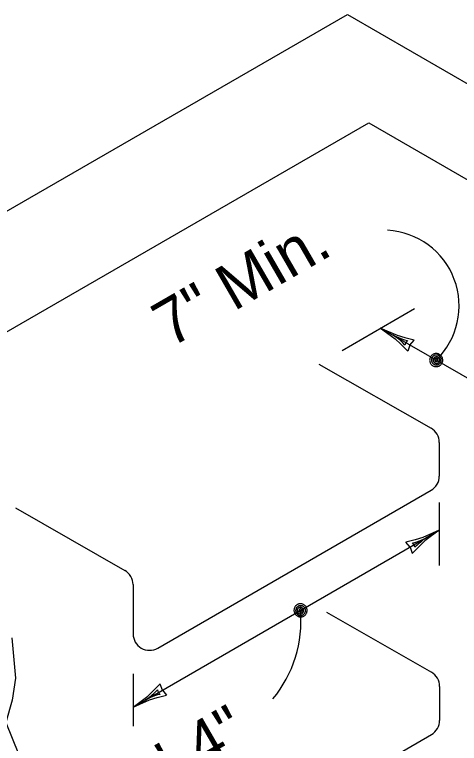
# Model space of a CAD drawing. Extents: x -7.1 to 10, y -5 to 6.
# Drawn here: x 3.017 to 3.657, y 3.525 to 4.574 of the extents above; entities that cross this region are included whole.
import ezdxf

# ---------------------------------------------------------------- set-up
doc = ezdxf.new("R2010")
doc.units = 0
for name, color, linetype in [('Level 4', 7, 'Continuous'), ('Level 6', 7, 'Continuous'), ('Level 7', 7, 'Continuous')]:
    doc.layers.add(name, color=color, linetype=linetype)

msp = doc.modelspace()

# ---------------------------------------------------------------- linework, layer by layer
at = {"layer": 'Level 4'}
for p, q in [((2.3265, 3.8986), (3.4958, 4.5737)), ((3.4958, 4.5737), (4.161, 4.1897)), ((2.6278, 3.899), (3.5265, 4.4179)), ((3.5265, 4.4179), (4.0246, 4.1304)), ((3.4545, 4.0707), (3.616, 3.9783)), ((3.6279, 3.9578), (3.6279, 3.9095)), ((3.2229, 3.662), (3.6161, 3.8891)), ((3.0185, 3.8636), (3.1755, 3.7737)), ((3.1874, 3.7532), (3.1874, 3.6824)), ((3.4656, 3.7135), (3.6165, 3.6272)), ((3.6284, 3.6067), (3.6284, 3.5579)), ((3.2494, 3.3255), (3.6166, 3.5375))]:
    msp.add_line(p, q, dxfattribs=at)
msp.add_lwpolyline([(3.0129, 3.6767), (3.0182, 3.6185), (3.0137, 3.5868), (3.0046, 3.555), (3.0227, 3.5097), (3.0273, 3.4961), (3.0227, 3.419), (3.0091, 3.3872), (3.0227, 3.292), (3.0227, 3.2466), (3.0091, 3.2285), (3.0273, 3.174), (3.0273, 3.1559), (3.0001, 3.0924), (3.0091, 3.047), (3.0182, 3.0198), (3.0137, 2.9654), (3.0156, 2.8939)], dxfattribs=at)
for centre, start, end in [((3.6043, 3.9578), 0, 60.2358), ((3.6043, 3.9095), 300.0053, 360), ((3.1638, 3.7532), 0, 60.2326), ((3.2111, 3.6824), 180, 300.0049), ((3.6048, 3.6067), 0, 60.239), ((3.6048, 3.5579), 300.0041, 360)]:
    msp.add_arc(centre, 0.0236, start, end, dxfattribs=at)
at = {"layer": 'Level 7'}
for p, q in [((3.4882, 4.0903), (3.592, 4.1509)), ((3.7166, 4.0226), (3.5435, 4.1226)), ((3.5854, 4.0981), (3.5916, 4.1051)), ((3.5854, 4.0981), (3.5825, 4.0893)), ((3.6279, 3.8715), (3.6279, 3.7806)), ((3.1874, 3.5771), (3.6279, 3.8315)), ((3.5858, 3.8073), (3.5797, 3.8143)), ((3.5858, 3.8073), (3.5887, 3.7986)), ((3.1874, 3.6251), (3.1874, 3.5493)), ((3.2296, 3.6012), (3.2266, 3.61)), ((3.2296, 3.6012), (3.2357, 3.5943))]:
    msp.add_line(p, q, dxfattribs=at)
for points in [[(3.5435, 4.1226), (3.5645, 4.1072), (3.5726, 4.0994), (3.5825, 4.0893)], [(3.5435, 4.1226), (3.5673, 4.1121), (3.5781, 4.1089), (3.5919, 4.1056)], [(3.5614, 4.1123), (3.5676, 4.1093), (3.5717, 4.1079), (3.5751, 4.1064), (3.5779, 4.1057), (3.5821, 4.1045), (3.5796, 4.1017), (3.5784, 4.098), (3.5761, 4.1009), (3.5741, 4.1028), (3.5719, 4.1045), (3.5699, 4.1064), (3.5679, 4.1078), (3.5656, 4.1095), (3.5614, 4.1123)], [(3.6279, 3.8315), (3.6041, 3.8209), (3.5933, 3.8178), (3.5797, 3.8143)], [(3.6279, 3.8315), (3.6069, 3.8161), (3.5988, 3.8083), (3.589, 3.798)], [(3.6101, 3.8211), (3.6044, 3.8172), (3.6011, 3.8143), (3.5982, 3.8122), (3.5961, 3.8101), (3.5929, 3.807), (3.5918, 3.8106), (3.5892, 3.8135), (3.5929, 3.814), (3.5955, 3.8148), (3.5981, 3.8159), (3.6007, 3.8167), (3.6029, 3.8177), (3.6056, 3.8188), (3.6101, 3.8211)], [(3.1874, 3.5771), (3.2085, 3.5925), (3.2166, 3.6003), (3.2263, 3.6106)], [(3.2053, 3.5874), (3.211, 3.5914), (3.2143, 3.5942), (3.2172, 3.5964), (3.2193, 3.5985), (3.2224, 3.6016), (3.2236, 3.598), (3.2262, 3.595), (3.2225, 3.5945), (3.2199, 3.5938), (3.2173, 3.5927), (3.2147, 3.5919), (3.2124, 3.5908), (3.2098, 3.5898), (3.2053, 3.5874)], [(3.1874, 3.5771), (3.2113, 3.5876), (3.2221, 3.5908), (3.2357, 3.5943)]]:
    msp.add_lwpolyline(points, dxfattribs=at)
for points in [[(3.6163, 4.0703), (3.6168, 4.0697), (3.6174, 4.0691), (3.6181, 4.0686), (3.6188, 4.0682), (3.6195, 4.0678), (3.6203, 4.0675), (3.6211, 4.0673), (3.6219, 4.0671), (3.6227, 4.067), (3.6235, 4.067), (3.6243, 4.067), (3.6251, 4.0671), (3.6259, 4.0673), (3.6267, 4.0676), (3.6275, 4.0679), (3.6282, 4.0683), (3.6289, 4.0687), (3.6296, 4.0692), (3.6302, 4.0698), (3.6307, 4.0704), (3.6312, 4.071), (3.6316, 4.0717), (3.632, 4.0725), (3.6323, 4.0732), (3.6326, 4.074), (3.6328, 4.0748), (3.6329, 4.0756), (3.6329, 4.0765), (3.6328, 4.0773), (3.6327, 4.0781), (3.6326, 4.0789), (3.6323, 4.0797), (3.632, 4.0804), (3.6316, 4.0812), (3.6311, 4.0819), (3.6306, 4.0825), (3.6301, 4.0831), (3.6295, 4.0837), (3.6288, 4.0842), (3.6281, 4.0846), (3.6274, 4.085), (3.6266, 4.0853), (3.6258, 4.0855), (3.625, 4.0857), (3.6242, 4.0858), (3.6234, 4.0858), (3.6226, 4.0858), (3.6218, 4.0857), (3.621, 4.0855), (3.6202, 4.0853), (3.6194, 4.0849), (3.6187, 4.0846), (3.618, 4.0841), (3.6173, 4.0836), (3.6168, 4.083), (3.6162, 4.0824), (3.6157, 4.0818), (3.6153, 4.0811), (3.6149, 4.0803), (3.6146, 4.0796), (3.6143, 4.0788), (3.6142, 4.078), (3.6141, 4.0772), (3.614, 4.0764), (3.6141, 4.0755), (3.6142, 4.0747), (3.6144, 4.0739), (3.6146, 4.0731), (3.6149, 4.0724), (3.6153, 4.0716), (3.6158, 4.071)], [(3.6183, 4.0721), (3.6188, 4.0716), (3.6192, 4.0712), (3.6197, 4.0708), (3.6202, 4.0705), (3.6208, 4.0702), (3.6213, 4.07), (3.6219, 4.0698), (3.6225, 4.0697), (3.6231, 4.0696), (3.6238, 4.0696), (3.6244, 4.0696), (3.625, 4.0697), (3.6256, 4.0698), (3.6262, 4.07), (3.6268, 4.0702), (3.6273, 4.0705), (3.6278, 4.0709), (3.6283, 4.0712), (3.6288, 4.0717), (3.6292, 4.0721), (3.6295, 4.0726), (3.6299, 4.0731), (3.6302, 4.0737), (3.6304, 4.0743), (3.6306, 4.0748), (3.6307, 4.0754), (3.6308, 4.0761), (3.6308, 4.0767), (3.6308, 4.0773), (3.6307, 4.0779), (3.6305, 4.0785), (3.6304, 4.0791), (3.6301, 4.0797), (3.6298, 4.0802), (3.6295, 4.0807), (3.6291, 4.0812), (3.6287, 4.0817), (3.6282, 4.0821), (3.6278, 4.0825), (3.6272, 4.0828), (3.6267, 4.0831), (3.6261, 4.0833), (3.6255, 4.0835), (3.6249, 4.0836), (3.6243, 4.0837), (3.6237, 4.0837), (3.6231, 4.0837), (3.6225, 4.0836), (3.6219, 4.0835), (3.6213, 4.0833), (3.6207, 4.083), (3.6201, 4.0827), (3.6196, 4.0824), (3.6191, 4.082), (3.6187, 4.0816), (3.6183, 4.0812), (3.6179, 4.0807), (3.6176, 4.0801), (3.6173, 4.0796), (3.6171, 4.079), (3.6169, 4.0784), (3.6168, 4.0778), (3.6167, 4.0772), (3.6166, 4.0766), (3.6167, 4.076), (3.6168, 4.0754), (3.6169, 4.0748), (3.6171, 4.0742), (3.6173, 4.0736), (3.6176, 4.0731), (3.6179, 4.0725)], [(3.6204, 4.0733), (3.6206, 4.073), (3.6209, 4.0727), (3.6213, 4.0725), (3.6216, 4.0723), (3.622, 4.0721), (3.6224, 4.0719), (3.6228, 4.0718), (3.6232, 4.0717), (3.6236, 4.0717), (3.624, 4.0717), (3.6244, 4.0717), (3.6248, 4.0717), (3.6252, 4.0718), (3.6256, 4.0719), (3.626, 4.0721), (3.6263, 4.0723), (3.6267, 4.0725), (3.627, 4.0728), (3.6273, 4.0731), (3.6276, 4.0734), (3.6278, 4.0737), (3.6281, 4.074), (3.6282, 4.0744), (3.6284, 4.0748), (3.6285, 4.0752), (3.6286, 4.0756), (3.6287, 4.076), (3.6287, 4.0764), (3.6286, 4.0768), (3.6286, 4.0772), (3.6285, 4.0776), (3.6284, 4.078), (3.6282, 4.0784), (3.628, 4.0788), (3.6278, 4.0791), (3.6276, 4.0794), (3.6273, 4.0797), (3.627, 4.08), (3.6266, 4.0803), (3.6263, 4.0805), (3.6259, 4.0807), (3.6255, 4.0808), (3.6251, 4.0809), (3.6247, 4.081), (3.6243, 4.0811), (3.6239, 4.0811), (3.6235, 4.0811), (3.6231, 4.081), (3.6227, 4.0809), (3.6223, 4.0808), (3.6219, 4.0806), (3.6216, 4.0804), (3.6212, 4.0802), (3.6209, 4.08), (3.6206, 4.0797), (3.6203, 4.0794), (3.6201, 4.0791), (3.6199, 4.0787), (3.6197, 4.0783), (3.6195, 4.078), (3.6194, 4.0776), (3.6193, 4.0772), (3.6193, 4.0768), (3.6192, 4.0763), (3.6193, 4.0759), (3.6193, 4.0755), (3.6194, 4.0751), (3.6195, 4.0747), (3.6197, 4.0744), (3.6199, 4.074), (3.6201, 4.0736)], [(3.6219, 4.0751), (3.6221, 4.075), (3.6222, 4.0748), (3.6224, 4.0747), (3.6226, 4.0746), (3.6227, 4.0745), (3.6229, 4.0744), (3.6231, 4.0744), (3.6233, 4.0743), (3.6235, 4.0743), (3.6237, 4.0743), (3.6239, 4.0743), (3.6241, 4.0743), (3.6243, 4.0744), (3.6245, 4.0744), (3.6247, 4.0745), (3.6249, 4.0746), (3.6251, 4.0747), (3.6253, 4.0748), (3.6254, 4.075), (3.6255, 4.0751), (3.6257, 4.0753), (3.6258, 4.0755), (3.6259, 4.0757), (3.6259, 4.0758), (3.626, 4.076), (3.6261, 4.0762), (3.6261, 4.0764), (3.6261, 4.0766), (3.6261, 4.0769), (3.626, 4.0771), (3.626, 4.0773), (3.6259, 4.0775), (3.6259, 4.0776), (3.6258, 4.0778), (3.6256, 4.078), (3.6255, 4.0782), (3.6254, 4.0783), (3.6252, 4.0784), (3.6251, 4.0786), (3.6249, 4.0787), (3.6247, 4.0788), (3.6245, 4.0789), (3.6243, 4.0789), (3.6241, 4.079), (3.6239, 4.079), (3.6237, 4.079), (3.6235, 4.079), (3.6233, 4.079), (3.6231, 4.0789), (3.6229, 4.0788), (3.6227, 4.0788), (3.6225, 4.0787), (3.6224, 4.0786), (3.6222, 4.0784), (3.622, 4.0783), (3.6219, 4.0781), (3.6218, 4.078), (3.6217, 4.0778), (3.6216, 4.0776), (3.6215, 4.0774), (3.6214, 4.0772), (3.6214, 4.077), (3.6214, 4.0768), (3.6214, 4.0766), (3.6214, 4.0764), (3.6214, 4.0762), (3.6214, 4.076), (3.6215, 4.0758), (3.6216, 4.0756), (3.6217, 4.0754), (3.6218, 4.0753)], [(3.4278, 3.7256), (3.4269, 3.7256), (3.4261, 3.7254), (3.4253, 3.7252), (3.4246, 3.7249), (3.4238, 3.7245), (3.4231, 3.7241), (3.4225, 3.7236), (3.4219, 3.7231), (3.4213, 3.7225), (3.4208, 3.7218), (3.4203, 3.7211), (3.4199, 3.7204), (3.4196, 3.7197), (3.4193, 3.7189), (3.4191, 3.7181), (3.419, 3.7173), (3.4189, 3.7164), (3.4189, 3.7156), (3.419, 3.7148), (3.4192, 3.714), (3.4194, 3.7132), (3.4197, 3.7124), (3.4201, 3.7117), (3.4205, 3.711), (3.421, 3.7103), (3.4215, 3.7097), (3.4221, 3.7091), (3.4228, 3.7086), (3.4235, 3.7082), (3.4242, 3.7078), (3.4249, 3.7074), (3.4257, 3.7072), (3.4265, 3.707), (3.4273, 3.7069), (3.4281, 3.7068), (3.429, 3.7068), (3.4298, 3.7069), (3.4306, 3.7071), (3.4314, 3.7073), (3.4322, 3.7076), (3.4329, 3.7079), (3.4336, 3.7084), (3.4343, 3.7089), (3.4349, 3.7094), (3.4354, 3.71), (3.436, 3.7106), (3.4364, 3.7113), (3.4368, 3.712), (3.4372, 3.7128), (3.4374, 3.7136), (3.4376, 3.7144), (3.4377, 3.7152), (3.4378, 3.716), (3.4378, 3.7168), (3.4377, 3.7176), (3.4375, 3.7185), (3.4373, 3.7192), (3.437, 3.72), (3.4366, 3.7208), (3.4362, 3.7215), (3.4357, 3.7221), (3.4352, 3.7227), (3.4346, 3.7233), (3.434, 3.7238), (3.4333, 3.7243), (3.4326, 3.7247), (3.4318, 3.725), (3.431, 3.7253), (3.4302, 3.7255), (3.4294, 3.7256), (3.4286, 3.7257)], [(3.4279, 3.7229), (3.4273, 3.7229), (3.4267, 3.7228), (3.4261, 3.7226), (3.4256, 3.7224), (3.425, 3.7221), (3.4245, 3.7218), (3.424, 3.7214), (3.4235, 3.721), (3.4231, 3.7206), (3.4227, 3.7201), (3.4223, 3.7196), (3.4221, 3.719), (3.4218, 3.7184), (3.4216, 3.7179), (3.4214, 3.7173), (3.4214, 3.7167), (3.4213, 3.716), (3.4213, 3.7154), (3.4214, 3.7148), (3.4215, 3.7142), (3.4217, 3.7136), (3.4219, 3.713), (3.4222, 3.7125), (3.4225, 3.7119), (3.4229, 3.7115), (3.4233, 3.711), (3.4237, 3.7106), (3.4242, 3.7102), (3.4247, 3.7098), (3.4253, 3.7095), (3.4258, 3.7093), (3.4264, 3.7091), (3.427, 3.7089), (3.4276, 3.7088), (3.4282, 3.7088), (3.4288, 3.7088), (3.4295, 3.7089), (3.4301, 3.709), (3.4307, 3.7092), (3.4312, 3.7094), (3.4318, 3.7097), (3.4323, 3.71), (3.4328, 3.7103), (3.4333, 3.7108), (3.4337, 3.7112), (3.4341, 3.7117), (3.4344, 3.7122), (3.4347, 3.7127), (3.435, 3.7133), (3.4352, 3.7139), (3.4353, 3.7145), (3.4354, 3.7151), (3.4355, 3.7157), (3.4354, 3.7163), (3.4354, 3.7169), (3.4353, 3.7175), (3.4351, 3.7181), (3.4349, 3.7187), (3.4346, 3.7193), (3.4343, 3.7198), (3.4339, 3.7203), (3.4335, 3.7208), (3.4331, 3.7212), (3.4326, 3.7216), (3.4321, 3.7219), (3.4315, 3.7222), (3.431, 3.7225), (3.4304, 3.7227), (3.4298, 3.7228), (3.4292, 3.7229), (3.4286, 3.7229)], [(3.4277, 3.7206), (3.4273, 3.7205), (3.4269, 3.7204), (3.4265, 3.7203), (3.4261, 3.7202), (3.4258, 3.72), (3.4254, 3.7198), (3.4251, 3.7195), (3.4248, 3.7193), (3.4245, 3.719), (3.4242, 3.7186), (3.424, 3.7183), (3.4238, 3.7179), (3.4236, 3.7176), (3.4235, 3.7172), (3.4234, 3.7168), (3.4234, 3.7164), (3.4233, 3.716), (3.4233, 3.7156), (3.4234, 3.7151), (3.4235, 3.7147), (3.4236, 3.7143), (3.4237, 3.714), (3.4239, 3.7136), (3.4241, 3.7132), (3.4244, 3.7129), (3.4246, 3.7126), (3.4249, 3.7123), (3.4252, 3.7121), (3.4256, 3.7118), (3.4259, 3.7116), (3.4263, 3.7115), (3.4267, 3.7113), (3.4271, 3.7112), (3.4275, 3.7112), (3.4279, 3.7111), (3.4283, 3.7111), (3.4288, 3.7112), (3.4292, 3.7113), (3.4296, 3.7114), (3.4299, 3.7115), (3.4303, 3.7117), (3.4307, 3.7119), (3.431, 3.7122), (3.4313, 3.7124), (3.4316, 3.7127), (3.4318, 3.7131), (3.4321, 3.7134), (3.4323, 3.7138), (3.4324, 3.7141), (3.4326, 3.7145), (3.4327, 3.7149), (3.4327, 3.7153), (3.4328, 3.7157), (3.4328, 3.7162), (3.4327, 3.7166), (3.4326, 3.717), (3.4325, 3.7174), (3.4324, 3.7177), (3.4322, 3.7181), (3.432, 3.7185), (3.4317, 3.7188), (3.4314, 3.7191), (3.4312, 3.7194), (3.4308, 3.7196), (3.4305, 3.7199), (3.4301, 3.7201), (3.4298, 3.7202), (3.4294, 3.7204), (3.429, 3.7205), (3.4286, 3.7205), (3.4281, 3.7206)], [(3.4282, 3.7182), (3.428, 3.7182), (3.4278, 3.7182), (3.4276, 3.7181), (3.4274, 3.718), (3.4273, 3.7179), (3.4271, 3.7178), (3.4269, 3.7177), (3.4268, 3.7176), (3.4266, 3.7174), (3.4265, 3.7173), (3.4264, 3.7171), (3.4263, 3.7169), (3.4262, 3.7167), (3.4261, 3.7165), (3.4261, 3.7163), (3.426, 3.7161), (3.426, 3.7159), (3.426, 3.7157), (3.4261, 3.7155), (3.4261, 3.7153), (3.4262, 3.7151), (3.4262, 3.7149), (3.4263, 3.7147), (3.4264, 3.7146), (3.4266, 3.7144), (3.4267, 3.7143), (3.4268, 3.7141), (3.427, 3.714), (3.4272, 3.7139), (3.4273, 3.7138), (3.4275, 3.7137), (3.4277, 3.7136), (3.4279, 3.7136), (3.4281, 3.7135), (3.4283, 3.7135), (3.4285, 3.7135), (3.4288, 3.7135), (3.4289, 3.7136), (3.4291, 3.7136), (3.4293, 3.7137), (3.4295, 3.7138), (3.4297, 3.7139), (3.4299, 3.714), (3.43, 3.7142), (3.4302, 3.7143), (3.4303, 3.7145), (3.4304, 3.7146), (3.4305, 3.7148), (3.4306, 3.715), (3.4307, 3.7152), (3.4307, 3.7154), (3.4307, 3.7156), (3.4308, 3.7158), (3.4307, 3.716), (3.4307, 3.7162), (3.4307, 3.7164), (3.4306, 3.7166), (3.4306, 3.7168), (3.4305, 3.717), (3.4304, 3.7172), (3.4302, 3.7173), (3.4301, 3.7175), (3.4299, 3.7176), (3.4298, 3.7178), (3.4296, 3.7179), (3.4294, 3.718), (3.4293, 3.7181), (3.4291, 3.7181), (3.4289, 3.7182), (3.4286, 3.7182), (3.4284, 3.7182)]]:
    msp.add_lwpolyline(points, close=True, dxfattribs=at)
for centre, radius, start, end in [((3.5475, 4.1545), 0.1089, 314.1942, 86.7956), ((3.252, 3.7014), 0.177, 320.5484, 4.821)]:
    msp.add_arc(centre, radius, start, end, dxfattribs=at)

# ---------------------------------------------------------------- texts
at = {"layer": 'Level 6'}
for s, rotation, p in [('7" Min.', 29.9994, (3.2412, 4.0934)), ('1\'-4"', 30.0006, (3.2044, 3.4378))]:
    msp.add_text(s, height=0.06613, rotation=rotation, dxfattribs=at).set_placement(p)

doc.saveas('drawing.dxf')
